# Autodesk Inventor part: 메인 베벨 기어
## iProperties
Created: 2014-10
Part Number: 메인 베벨 기어
Material: Steel, Mild
Document SubType Name: Modeling
Designer: KYOUNG IL JANG
Categories: <?xml version="1.0" encoding="UTF-16"?> <MemberInstance><Categories><FamilyTemplate><FamilyTemplateParameter ValueType="xs:double" Id="1" ObjectReferenceKey="da
Mass: 269.583 g
Surface Area: 108.837 cm^2
Volume: 34.2981 cm^3
Density: 7.86 g/cm^3
CustomPartVersion: 1
Company: 한국ATC센터
Author: KYOUNG IL JANG
Revision Number: 1
